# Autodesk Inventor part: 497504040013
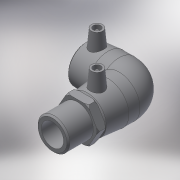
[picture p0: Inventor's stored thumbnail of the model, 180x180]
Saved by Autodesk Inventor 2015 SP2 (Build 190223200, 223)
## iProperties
Created: 2017-06
Part Number: 497504040013
Material: Generic
Description: PE Male Transition Elbow 90° 40x1 1_4
Document SubType Name: Modeling
Designer: KIM
Mass: 242.988 g
Surface Area: 557.528 cm^2
Volume: 242.988 cm^3
Density: 1 g/cm^3
Appearance: Default
Author: KIM
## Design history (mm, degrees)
derived "497504.ipt"
feature "Solid1::497504.ipt"
feature "Solid2::497504.ipt"
tag "TaggingFeature1"
workplane "Work Plane2"
body "Solid1"
body "Solid2"
other parameters: "d2" = 55, "d4" = 29.33333, "d5" = 49.5, "d8" = 168 deg, "d10" = 17.6, "d11" = 5.86667, "d29" = 47, "d30" = 15, "d31" = 45.76, "d34" = 5 deg, "d41" = 4, "d42" = 14, "d43" = 0, "d48" = 60.5, "d50" = 4, "d51" = 17.6, "d52" = 44, "d54" = 90 deg, "d86" = 3, "d87" = 0, "d93" = 0.1, "d94" = 11, "d95" = 41.91, "d96" = 29.337, "d98" = 44, "d99" = 55, "d100" = 39.6, "d102" = 2, "d106" = 0, "d108" = 39.6, "d114" = 44, "d115" = 0, "d116" = -44, "L_" = 132, "L_1" = 44, "A_" = 47, "d_2" = 12, "L_2" = 44, "D_1" = 55, "R_" = 41.91
